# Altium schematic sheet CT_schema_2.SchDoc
size 316 x 185 mm
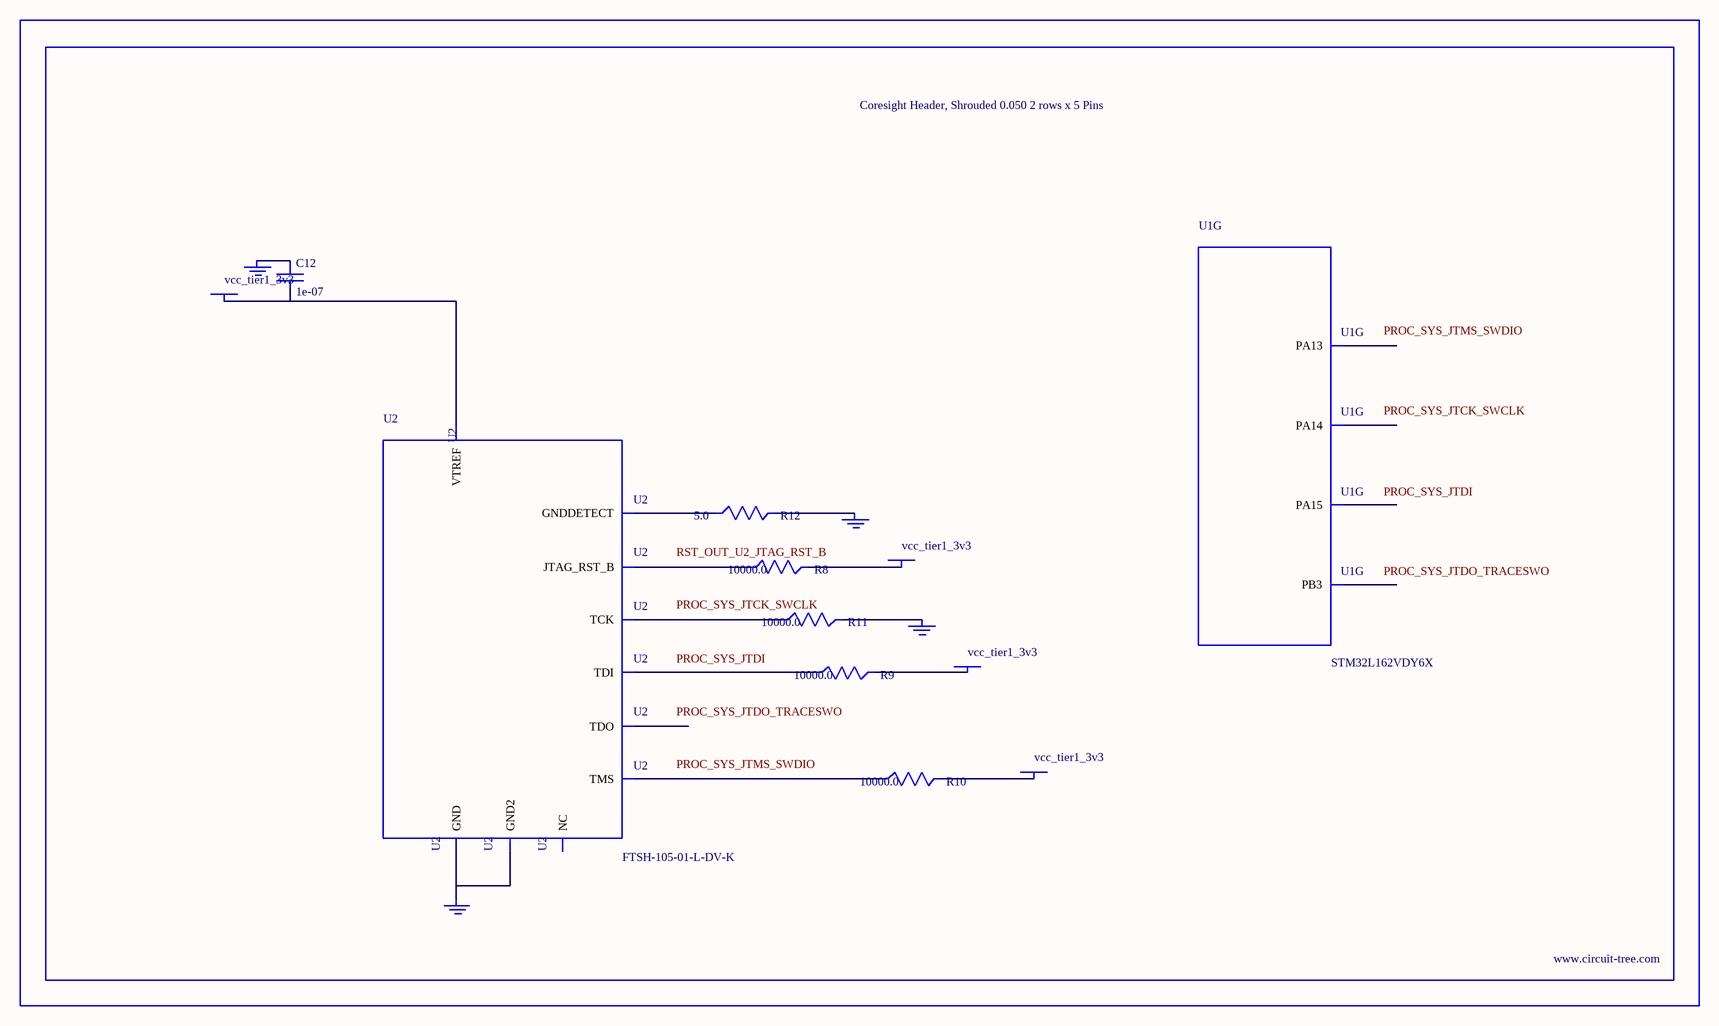
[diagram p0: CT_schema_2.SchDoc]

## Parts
BORDER1  (no value)
C12  1e-07  [C0402]
GND_INSTANCE_1_0  (no value)
GND_INSTANCE_1_1  (no value)
GND_INSTANCE_1_2  (no value)
GND_INSTANCE_1_3  (no value)
POWER_INSTANCE_1_0  vcc_tier1_3v3
POWER_INSTANCE_1_1  vcc_tier1_3v3
POWER_INSTANCE_1_2  vcc_tier1_3v3
POWER_INSTANCE_1_3  vcc_tier1_3v3
R8  10000.0  [R0603]
R9  10000.0  [R0603]
R10  10000.0  [R0603]
R11  10000.0  [R0603]
R12  5.0  [R0603]
U1  STM32L162VDY6X  [WLCSP104]  (part G of 9)
U2  FTSH-105-01-L-DV-K  [SAMTEC_FTSH-105-01-L-DV-K]

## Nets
NetC12_1: C12.1 GND_INSTANCE_1_0.0(GND)
NetC12_2: C12.2 POWER_INSTANCE_1_0.0(PWR) U2.1(VTREF)
NetGND_INSTANCE_1_1_0: GND_INSTANCE_1_1.0(GND) R11.2
NetGND_INSTANCE_1_2_0: GND_INSTANCE_1_2.0(GND) R12.2
NetGND_INSTANCE_1_3_0: GND_INSTANCE_1_3.0(GND) U2.3(GND) U2.5(GND2)
NetPOWER_INSTANCE_1_1_0: POWER_INSTANCE_1_1.0(PWR) R10.2
NetPOWER_INSTANCE_1_2_0: POWER_INSTANCE_1_2.0(PWR) R9.2
NetPOWER_INSTANCE_1_3_0: POWER_INSTANCE_1_3.0(PWR) R8.2
NetR8_1: R8.1 U2.10(JTAG_RST_B)
NetR9_1: R9.1 U2.8(TDI)
NetR10_1: R10.1 U2.2(TMS)
NetR11_1: R11.1 U2.4(TCK)
NetR12_1: R12.1 U2.9(GNDDETECT)

Not connected (* = marked no-connect by the designer): U1 B1(PA15) B5(PB3) D3(PA14) E3(PA13); U2 6(TDO) 7(NC)

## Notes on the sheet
- Labels drawn without touching a wire or pin: PROC_SYS_JTCK_SWCLK, PROC_SYS_JTDI, PROC_SYS_JTDO_TRACESWO, PROC_SYS_JTMS_SWDIO, RST_OUT_U2_JTAG_RST_B

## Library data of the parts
BORDER1 = BORDER_PAGE1
C12 = C0402C104K3RACTU
GND_INSTANCE_1_0-GND_INSTANCE_1_3 = GND
POWER_INSTANCE_1_0-POWER_INSTANCE_1_3 = PWR
R8-R11 = RC0603JR-0710KL
R12 = ERJ-3GEYJ5R1V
